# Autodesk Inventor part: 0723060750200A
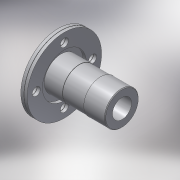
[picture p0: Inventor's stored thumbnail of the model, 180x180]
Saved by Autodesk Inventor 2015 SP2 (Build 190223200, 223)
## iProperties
Created: 2017-02
Part Number: 0723060750200A
Material: PVC-Piping
Description: PLASSON FLANGE ADAPTOR WITH METAL FLANGE 75-2"
Document SubType Name: Modeling
Designer: KIM
Mass: 92.6774 g
Surface Area: 199.44 cm^2
Volume: 66.1981 cm^3
Density: 1.4 g/cm^3
Appearance: Smooth - White
Author: Кирилл
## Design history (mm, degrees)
derived "872306.ipt"
feature "Solid1::872306.ipt"
tag "TaggingFeature1"
body "Solid1"
other parameters: "d73" = 14.2, "d74" = 90 deg, "d75" = 0.3, "d76" = 165, "d77" = 18, "d78" = 62.5, "d80" = 0, "d82" = 360 deg, "d96" = 0.3, "d99" = 360 deg, "d101" = 75, "d103" = 142, "d104" = 1.5, "d107" = 97.5, "d108" = 3.55, "d116" = 73.5, "d117" = 47.33333, "d118" = 47.33333, "d119" = 75, "d120" = 3.75, "d_" = 75, "H_" = 142, "D_" = 165, "Dp_" = 125, "S_" = 18
